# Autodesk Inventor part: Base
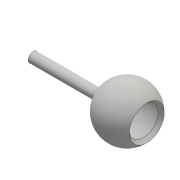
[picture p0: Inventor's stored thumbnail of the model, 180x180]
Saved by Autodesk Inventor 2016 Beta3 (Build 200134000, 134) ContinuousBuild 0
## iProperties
Created: 2016-03
Part Number: Base
Material: Generic
Document SubType Name: Modeling
Designer: Gaurav
Density: 1 g/cm^3
Appearance: Default
Author: Gaurav
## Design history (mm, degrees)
sketch "Sketch1"
  geometry: L1 (-15, 0)-(-12.5, 0); L2 (9.367, 8.277)-(11.24, 9.933); A1 r 12.5 centre (0, 0) between (9.367, 8.277) and (-12.5, 0); A2 r 15 centre (0, 0) between (11.24, 9.933) and (-15, 0); 1 further point
  constraints: 4 end point, 4 point on circle, 2 centre point, 2 coincident, 1 horizontal
  dimensions: "d0" = 25 diameter of A1; "d1" = 30 diameter of A2
revolve "Revolution1" sketch "Sketch1" stored, may be unused: angle "d2" = 90 deg
sketch "Sketch2"
  geometry: C1 r 2.85 at (0, 0); 1 further point
  constraints: 1 centre point, 1 coincident
extrude "Extrusion1" join sketch "Sketch2" distance "d3" = 53.5; taper "d4" = 0 deg
delete_face "Delete Face2"
body "Solid1"
